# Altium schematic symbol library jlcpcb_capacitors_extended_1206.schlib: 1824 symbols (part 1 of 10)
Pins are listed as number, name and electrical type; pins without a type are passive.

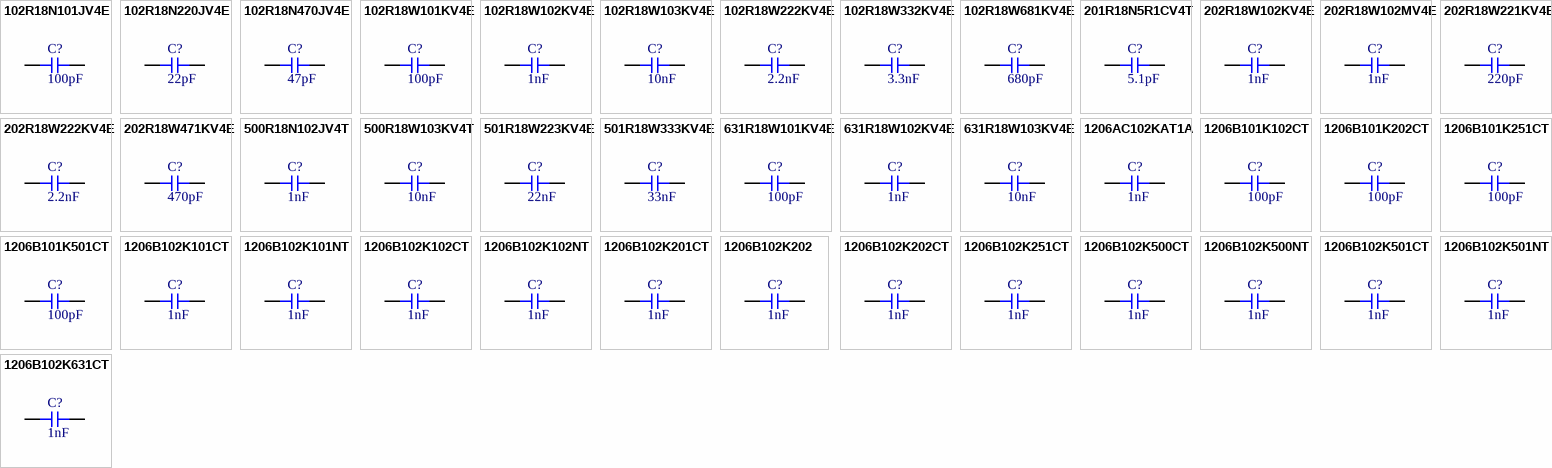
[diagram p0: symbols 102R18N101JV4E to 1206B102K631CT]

## 102R18N101JV4E
designator C?  Capacitance: 100pF  (hidden comment: *)
Capacitor, Ceramic (MLCC), 100pF, ±5%, 1kV, C0G, ±5%, SMD 1206; Manufacturer: Johanson Dielectrics; Manufacturer Part Number: 102R18N101JV4E
footprint CAP-1206 (1206 (3216M) Capacitor)
pins: 1, 2

## 102R18N220JV4E
designator C?  Capacitance: 22pF  (hidden comment: *)
Capacitor, Ceramic (MLCC), 22pF, ±5%, 1kV, NP0, ±5%, SMD 1206; Manufacturer: Johanson Dielectrics; Manufacturer Part Number: 102R18N220JV4E
footprint CAP-1206 (1206 (3216M) Capacitor)
pins: 1, 2

## 102R18N470JV4E
designator C?  Capacitance: 47pF  (hidden comment: *)
Capacitor, Ceramic (MLCC), 47pF, ±5%, 1kV, NP0, ±5%, SMD 1206; Manufacturer: Johanson Dielectrics; Manufacturer Part Number: 102R18N470JV4E
footprint CAP-1206 (1206 (3216M) Capacitor)
pins: 1, 2

## 102R18W101KV4E
designator C?  Capacitance: 100pF  (hidden comment: *)
Capacitor, Ceramic (MLCC), 100pF, ±10%, 1kV, X7R, ±10%, SMD 1206; Manufacturer: Johanson Dielectrics; Manufacturer Part Number: 102R18W101KV4E
footprint CAP-1206 (1206 (3216M) Capacitor)
pins: 1, 2

## 102R18W102KV4E
designator C?  Capacitance: 1nF  (hidden comment: *)
Capacitor, Ceramic (MLCC), 1nF, ±10%, 1kV, X7R, ±10%, SMD 1206; Manufacturer: Johanson Dielectrics; Manufacturer Part Number: 102R18W102KV4E
footprint CAP-1206 (1206 (3216M) Capacitor)
pins: 1, 2

## 102R18W103KV4E
designator C?  Capacitance: 10nF  (hidden comment: *)
Capacitor, Ceramic (MLCC), 10nF, ±10%, 1kV, X7R, ±10%, SMD 1206; Manufacturer: Johanson Dielectrics; Manufacturer Part Number: 102R18W103KV4E
footprint CAP-1206 (1206 (3216M) Capacitor)
pins: 1, 2

## 102R18W222KV4E
designator C?  Capacitance: 2.2nF  (hidden comment: *)
Capacitor, Ceramic (MLCC), 2.2nF, ±10%, 1kV, X7R, ±10%, SMD 1206; Manufacturer: Johanson Dielectrics; Manufacturer Part Number: 102R18W222KV4E
footprint CAP-1206 (1206 (3216M) Capacitor)
pins: 1, 2

## 102R18W332KV4E
designator C?  Capacitance: 3.3nF  (hidden comment: *)
Capacitor, Ceramic (MLCC), 3.3nF, ±10%, 1kV, X7R, ±10%, SMD 1206; Manufacturer: Johanson Dielectrics; Manufacturer Part Number: 102R18W332KV4E
footprint CAP-1206 (1206 (3216M) Capacitor)
pins: 1, 2

## 102R18W681KV4E
designator C?  Capacitance: 680pF  (hidden comment: *)
Capacitor, Ceramic (MLCC), 680pF, ±10%, 1kV, X7R, ±10%, SMD 1206; Manufacturer: Johanson Dielectrics; Manufacturer Part Number: 102R18W681KV4E
footprint CAP-1206 (1206 (3216M) Capacitor)
pins: 1, 2

## 201R18N5R1CV4T
designator C?  Capacitance: 5.1pF  (hidden comment: *)
Capacitor, Ceramic (MLCC), 5.1pF, ±0.25pF, 200V, NP0, ±0.25pF, SMD 1206; Manufacturer: Johanson Dielectrics; Manufacturer Part Number: 201R18N5R1CV4T
footprint CAP-1206 (1206 (3216M) Capacitor)
pins: 1, 2

## 202R18W102KV4E
designator C?  Capacitance: 1nF  (hidden comment: *)
Capacitor, Ceramic (MLCC), 1nF, ±10%, 2kV, X7R, ±10%, SMD 1206; Manufacturer: Johanson Dielectrics; Manufacturer Part Number: 202R18W102KV4E
footprint CAP-1206 (1206 (3216M) Capacitor)
pins: 1, 2

## 202R18W102MV4E
designator C?  Capacitance: 1nF  (hidden comment: *)
Capacitor, Ceramic (MLCC), 1nF, ±20%, 2kV, X7R, ±20%, SMD 1206; Manufacturer: Johanson Dielectrics; Manufacturer Part Number: 202R18W102MV4E
footprint CAP-1206 (1206 (3216M) Capacitor)
pins: 1, 2

## 202R18W221KV4E
designator C?  Capacitance: 220pF  (hidden comment: *)
Capacitor, Ceramic (MLCC), 220pF, ±10%, 2kV, X7R, ±10%, SMD 1206; Manufacturer: Johanson Dielectrics; Manufacturer Part Number: 202R18W221KV4E
footprint CAP-1206 (1206 (3216M) Capacitor)
pins: 1, 2

## 202R18W222KV4E
designator C?  Capacitance: 2.2nF  (hidden comment: *)
Capacitor, Ceramic (MLCC), 2.2nF, ±10%, 2kV, X7R, ±10%, SMD 1206; Manufacturer: Johanson Dielectrics; Manufacturer Part Number: 202R18W222KV4E
footprint CAP-1206 (1206 (3216M) Capacitor)
pins: 1, 2

## 202R18W471KV4E
designator C?  Capacitance: 470pF  (hidden comment: *)
Capacitor, Ceramic (MLCC), 470pF, ±10%, 2kV, X7R, ±10%, SMD 1206; Manufacturer: Johanson Dielectrics; Manufacturer Part Number: 202R18W471KV4E
footprint CAP-1206 (1206 (3216M) Capacitor)
pins: 1, 2

## 500R18N102JV4T
designator C?  Capacitance: 1nF  (hidden comment: *)
Capacitor, Ceramic (MLCC), 1nF, ±5%, 50V, NP0, ±5%, SMD 1206; Manufacturer: Johanson Dielectrics; Manufacturer Part Number: 500R18N102JV4T
footprint CAP-1206 (1206 (3216M) Capacitor)
pins: 1, 2

## 500R18W103KV4T
designator C?  Capacitance: 10nF  (hidden comment: *)
Capacitor, Ceramic (MLCC), 10nF, ±10%, 50V, X7R, ±10%, SMD 1206; Manufacturer: Johanson Dielectrics; Manufacturer Part Number: 500R18W103KV4T
footprint CAP-1206 (1206 (3216M) Capacitor)
pins: 1, 2

## 501R18W223KV4E
designator C?  Capacitance: 22nF  (hidden comment: *)
Capacitor, Ceramic (MLCC), 22nF, ±10%, 500V, X7R, ±10%, SMD 1206; Manufacturer: Johanson Dielectrics; Manufacturer Part Number: 501R18W223KV4E
footprint CAP-1206 (1206 (3216M) Capacitor)
pins: 1, 2

## 501R18W333KV4E
designator C?  Capacitance: 33nF  (hidden comment: *)
Capacitor, Ceramic (MLCC), 33nF, ±10%, 500V, X7R, ±10%, SMD 1206; Manufacturer: Johanson Dielectrics; Manufacturer Part Number: 501R18W333KV4E
footprint CAP-1206 (1206 (3216M) Capacitor)
pins: 1, 2

## 631R18W101KV4E
designator C?  Capacitance: 100pF  (hidden comment: *)
Capacitor, Ceramic (MLCC), 100pF, ±10%, 630V, X7R, ±10%, SMD 1206; Manufacturer: Johanson Dielectrics; Manufacturer Part Number: 631R18W101KV4E
footprint CAP-1206 (1206 (3216M) Capacitor)
pins: 1, 2

## 631R18W102KV4E
designator C?  Capacitance: 1nF  (hidden comment: *)
Capacitor, Ceramic (MLCC), 1nF, ±10%, 630V, X7R, ±10%, SMD 1206; Manufacturer: Johanson Dielectrics; Manufacturer Part Number: 631R18W102KV4E
footprint CAP-1206 (1206 (3216M) Capacitor)
pins: 1, 2

## 631R18W103KV4E
designator C?  Capacitance: 10nF  (hidden comment: *)
Capacitor, Ceramic (MLCC), 10nF, ±10%, 630V, X7R, ±10%, SMD 1206; Manufacturer: Johanson Dielectrics; Manufacturer Part Number: 631R18W103KV4E
footprint CAP-1206 (1206 (3216M) Capacitor)
pins: 1, 2

## 1206AC102KAT1A
designator C?  Capacitance: 1nF  (hidden comment: *)
Capacitor, Ceramic (MLCC), 1nF, ±10%, 1kV, X7R, ±10%, SMD 1206; Manufacturer: AVX; Manufacturer Part Number: 1206AC102KAT1A
footprint CAP-1206 (1206 (3216M) Capacitor)
pins: 1, 2

## 1206B101K102CT
designator C?  Capacitance: 100pF  (hidden comment: *)
Capacitor, Ceramic (MLCC), 100pF, ±10%, 1kV, X7R, ±10%, SMD 1206; Manufacturer: Walsin Tech Corp; Manufacturer Part Number: 1206B101K102CT
footprint CAP-1206 (1206 (3216M) Capacitor)
pins: 1, 2

## 1206B101K202CT
designator C?  Capacitance: 100pF  (hidden comment: *)
Capacitor, Ceramic (MLCC), 100pF, ±10%, 2kV, X7R, ±10%, SMD 1206; Manufacturer: Walsin Tech Corp; Manufacturer Part Number: 1206B101K202CT
footprint CAP-1206 (1206 (3216M) Capacitor)
pins: 1, 2

## 1206B101K251CT
designator C?  Capacitance: 100pF  (hidden comment: *)
Capacitor, Ceramic (MLCC), 100pF, ±10%, 250V, X7R, ±10%, SMD 1206; Manufacturer: Walsin Tech Corp; Manufacturer Part Number: 1206B101K251CT
footprint CAP-1206 (1206 (3216M) Capacitor)
pins: 1, 2

## 1206B101K501CT
designator C?  Capacitance: 100pF  (hidden comment: *)
Capacitor, Ceramic (MLCC), 100pF, ±10%, 500V, X7R, ±10%, SMD 1206; Manufacturer: Walsin Tech Corp; Manufacturer Part Number: 1206B101K501CT
footprint CAP-1206 (1206 (3216M) Capacitor)
pins: 1, 2

## 1206B102K101CT
designator C?  Capacitance: 1nF  (hidden comment: *)
Capacitor, Ceramic (MLCC), 1nF, ±10%, 100V, X7R, ±10%, SMD 1206; Manufacturer: Walsin Tech Corp; Manufacturer Part Number: 1206B102K101CT
footprint CAP-1206 (1206 (3216M) Capacitor)
pins: 1, 2

## 1206B102K101NT
designator C?  Capacitance: 1nF  (hidden comment: *)
Capacitor, Ceramic (MLCC), 1nF, ±10%, 100V, X7R, ±10%, SMD 1206; Manufacturer: FH(Guangdong Fenghua Advanced Tech); Manufacturer Part Number: 1206B102K101NT
footprint CAP-1206 (1206 (3216M) Capacitor)
pins: 1, 2

## 1206B102K102CT
designator C?  Capacitance: 1nF  (hidden comment: *)
Capacitor, Ceramic (MLCC), 1nF, ±10%, 1kV, X7R, ±10%, SMD 1206; Manufacturer: Walsin Tech Corp; Manufacturer Part Number: 1206B102K102CT
footprint CAP-1206 (1206 (3216M) Capacitor)
pins: 1, 2

## 1206B102K102NT
designator C?  Capacitance: 1nF  (hidden comment: *)
Capacitor, Ceramic (MLCC), 1nF, ±10%, 1kV, X7R, ±10%, SMD 1206; Manufacturer: FH(Guangdong Fenghua Advanced Tech); Manufacturer Part Number: 1206B102K102NT
footprint CAP-1206 (1206 (3216M) Capacitor)
pins: 1, 2

## 1206B102K201CT
designator C?  Capacitance: 1nF  (hidden comment: *)
Capacitor, Ceramic (MLCC), 1nF, ±10%, 200V, X7R, ±10%, SMD 1206; Manufacturer: Walsin Tech Corp; Manufacturer Part Number: 1206B102K201CT
footprint CAP-1206 (1206 (3216M) Capacitor)
pins: 1, 2

## 1206B102K202
designator C?  Capacitance: 1nF  (hidden comment: *)
Capacitor, Ceramic (MLCC), 1nF, ±10%, 2kV, X7R, ±10%, SMD 1206; Manufacturer: Walsin Tech Corp; Manufacturer Part Number: 1206B102K202
footprint CAP-1206 (1206 (3216M) Capacitor)
pins: 1, 2

## 1206B102K202CT
designator C?  Capacitance: 1nF  (hidden comment: *)
Capacitor, Ceramic (MLCC), 1nF, ±10%, 2kV, X7R, ±10%, SMD 1206; Manufacturer: Walsin Tech Corp; Manufacturer Part Number: 1206B102K202CT
footprint CAP-1206 (1206 (3216M) Capacitor)
pins: 1, 2

## 1206B102K251CT
designator C?  Capacitance: 1nF  (hidden comment: *)
Capacitor, Ceramic (MLCC), 1nF, ±10%, 250V, X7R, ±10%, SMD 1206; Manufacturer: Walsin Tech Corp; Manufacturer Part Number: 1206B102K251CT
footprint CAP-1206 (1206 (3216M) Capacitor)
pins: 1, 2

## 1206B102K500CT
designator C?  Capacitance: 1nF  (hidden comment: *)
Capacitor, Ceramic (MLCC), 1nF, ±10%, 50V, X7R, ±10%, SMD 1206; Manufacturer: Walsin Tech Corp; Manufacturer Part Number: 1206B102K500CT
footprint CAP-1206 (1206 (3216M) Capacitor)
pins: 1, 2

## 1206B102K500NT
designator C?  Capacitance: 1nF  (hidden comment: *)
Capacitor, Ceramic (MLCC), 1nF, ±10%, 50V, X7R, ±10%, SMD 1206; Manufacturer: FH(Guangdong Fenghua Advanced Tech); Manufacturer Part Number: 1206B102K500NT
footprint CAP-1206 (1206 (3216M) Capacitor)
pins: 1, 2

## 1206B102K501CT
designator C?  Capacitance: 1nF  (hidden comment: *)
Capacitor, Ceramic (MLCC), 1nF, ±10%, 500V, X7R, ±10%, SMD 1206; Manufacturer: Walsin Tech Corp; Manufacturer Part Number: 1206B102K501CT
footprint CAP-1206 (1206 (3216M) Capacitor)
pins: 1, 2

## 1206B102K501NT
designator C?  Capacitance: 1nF  (hidden comment: *)
Capacitor, Ceramic (MLCC), 1nF, ±10%, 500V, X7R, ±10%, SMD 1206; Manufacturer: FH(Guangdong Fenghua Advanced Tech); Manufacturer Part Number: 1206B102K501NT
footprint CAP-1206 (1206 (3216M) Capacitor)
pins: 1, 2

## 1206B102K631CT
designator C?  Capacitance: 1nF  (hidden comment: *)
Capacitor, Ceramic (MLCC), 1nF, ±10%, 630V, X7R, ±10%, SMD 1206; Manufacturer: Walsin Tech Corp; Manufacturer Part Number: 1206B102K631CT
footprint CAP-1206 (1206 (3216M) Capacitor)
pins: 1, 2

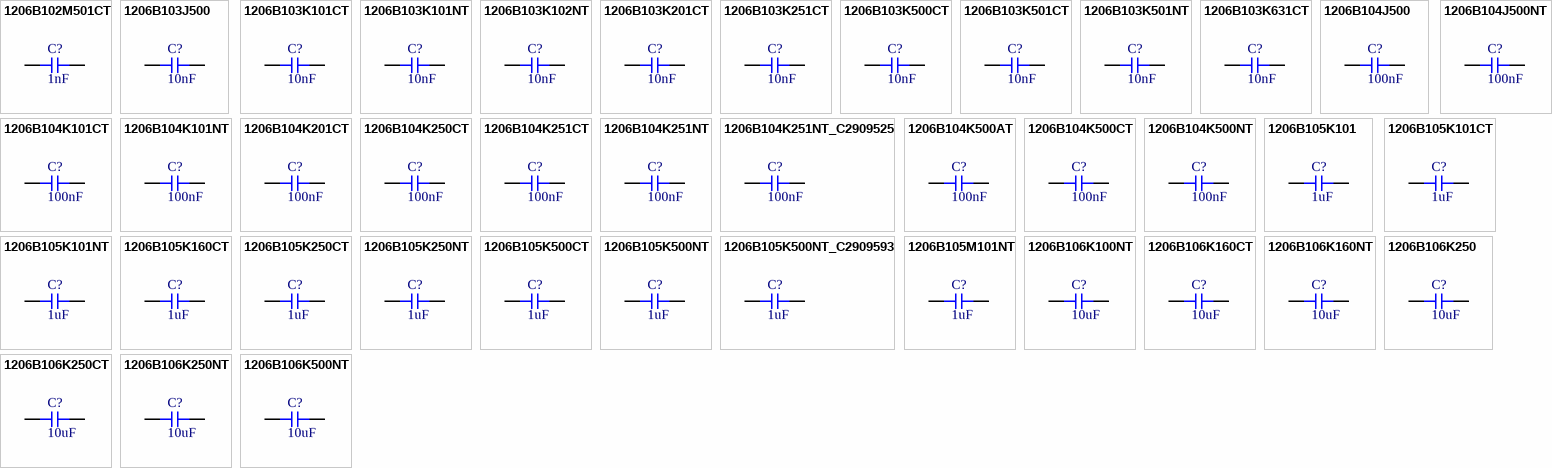
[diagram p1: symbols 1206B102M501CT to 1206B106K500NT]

## 1206B102M501CT
designator C?  Capacitance: 1nF  (hidden comment: *)
Capacitor, Ceramic (MLCC), 1nF, ±20%, 500V, X7R, ±20%, SMD 1206; Manufacturer: Walsin Tech Corp; Manufacturer Part Number: 1206B102M501CT
footprint CAP-1206 (1206 (3216M) Capacitor)
pins: 1, 2

## 1206B103J500
designator C?  Capacitance: 10nF  (hidden comment: *)
Capacitor, Ceramic (MLCC), 10nF, ±5%, 50V, X7R, ±5%, SMD 1206; Manufacturer: Walsin Tech Corp; Manufacturer Part Number: 1206B103J500
footprint CAP-1206 (1206 (3216M) Capacitor)
pins: 1, 2

## 1206B103K101CT
designator C?  Capacitance: 10nF  (hidden comment: *)
Capacitor, Ceramic (MLCC), 10nF, ±10%, 100V, X7R, ±10%, SMD 1206; Manufacturer: Walsin Tech Corp; Manufacturer Part Number: 1206B103K101CT
footprint CAP-1206 (1206 (3216M) Capacitor)
pins: 1, 2

## 1206B103K101NT
designator C?  Capacitance: 10nF  (hidden comment: *)
Capacitor, Ceramic (MLCC), 10nF, ±10%, 100V, X7R, ±10%, SMD 1206; Manufacturer: FH(Guangdong Fenghua Advanced Tech); Manufacturer Part Number: 1206B103K101NT
footprint CAP-1206 (1206 (3216M) Capacitor)
pins: 1, 2

## 1206B103K102NT
designator C?  Capacitance: 10nF  (hidden comment: *)
Capacitor, Ceramic (MLCC), 10nF, ±10%, 1kV, X7R, ±10%, SMD 1206; Manufacturer: FH(Guangdong Fenghua Advanced Tech); Manufacturer Part Number: 1206B103K102NT
footprint CAP-1206 (1206 (3216M) Capacitor)
pins: 1, 2

## 1206B103K201CT
designator C?  Capacitance: 10nF  (hidden comment: *)
Capacitor, Ceramic (MLCC), 10nF, ±10%, 200V, X7R, ±10%, SMD 1206; Manufacturer: Walsin Tech Corp; Manufacturer Part Number: 1206B103K201CT
footprint CAP-1206 (1206 (3216M) Capacitor)
pins: 1, 2

## 1206B103K251CT
designator C?  Capacitance: 10nF  (hidden comment: *)
Capacitor, Ceramic (MLCC), 10nF, ±10%, 250V, X7R, ±10%, SMD 1206; Manufacturer: Walsin Tech Corp; Manufacturer Part Number: 1206B103K251CT
footprint CAP-1206 (1206 (3216M) Capacitor)
pins: 1, 2

## 1206B103K500CT
designator C?  Capacitance: 10nF  (hidden comment: *)
Capacitor, Ceramic (MLCC), 10nF, ±10%, 50V, X7R, ±10%, SMD 1206; Manufacturer: Walsin Tech Corp; Manufacturer Part Number: 1206B103K500CT
footprint CAP-1206 (1206 (3216M) Capacitor)
pins: 1, 2

## 1206B103K501CT
designator C?  Capacitance: 10nF  (hidden comment: *)
Capacitor, Ceramic (MLCC), 10nF, ±10%, 500V, X7R, ±10%, SMD 1206; Manufacturer: Walsin Tech Corp; Manufacturer Part Number: 1206B103K501CT
footprint CAP-1206 (1206 (3216M) Capacitor)
pins: 1, 2

## 1206B103K501NT
designator C?  Capacitance: 10nF  (hidden comment: *)
Capacitor, Ceramic (MLCC), 10nF, ±10%, 500V, X7R, ±10%, SMD 1206; Manufacturer: FH(Guangdong Fenghua Advanced Tech); Manufacturer Part Number: 1206B103K501NT
footprint CAP-1206 (1206 (3216M) Capacitor)
pins: 1, 2

## 1206B103K631CT
designator C?  Capacitance: 10nF  (hidden comment: *)
Capacitor, Ceramic (MLCC), 10nF, ±10%, 630V, X7R, ±10%, SMD 1206; Manufacturer: Walsin Tech Corp; Manufacturer Part Number: 1206B103K631CT
footprint CAP-1206 (1206 (3216M) Capacitor)
pins: 1, 2

## 1206B104J500
designator C?  Capacitance: 100nF  (hidden comment: *)
Capacitor, Ceramic (MLCC), 100nF, ±5%, 50V, X7R, ±5%, SMD 1206; Manufacturer: Walsin Tech Corp; Manufacturer Part Number: 1206B104J500
footprint CAP-1206 (1206 (3216M) Capacitor)
pins: 1, 2

## 1206B104J500NT
designator C?  Capacitance: 100nF  (hidden comment: *)
Capacitor, Ceramic (MLCC), 100nF, ±5%, 50V, ±5%, SMD 1206; Manufacturer: FH(Guangdong Fenghua Advanced Tech); Manufacturer Part Number: 1206B104J500NT
footprint CAP-1206 (1206 (3216M) Capacitor)
pins: 1, 2

## 1206B104K101CT
designator C?  Capacitance: 100nF  (hidden comment: *)
Capacitor, Ceramic (MLCC), 100nF, ±10%, 100V, X7R, ±10%, SMD 1206; Manufacturer: Walsin Tech Corp; Manufacturer Part Number: 1206B104K101CT
footprint CAP-1206 (1206 (3216M) Capacitor)
pins: 1, 2

## 1206B104K101NT
designator C?  Capacitance: 100nF  (hidden comment: *)
Capacitor, Ceramic (MLCC), 100nF, ±10%, 100V, X7R, ±10%, SMD 1206; Manufacturer: FH(Guangdong Fenghua Advanced Tech); Manufacturer Part Number: 1206B104K101NT
footprint CAP-1206 (1206 (3216M) Capacitor)
pins: 1, 2

## 1206B104K201CT
designator C?  Capacitance: 100nF  (hidden comment: *)
Capacitor, Ceramic (MLCC), 100nF, ±10%, 200V, X7R, ±10%, SMD 1206; Manufacturer: Walsin Tech Corp; Manufacturer Part Number: 1206B104K201CT
footprint CAP-1206 (1206 (3216M) Capacitor)
pins: 1, 2

## 1206B104K250CT
designator C?  Capacitance: 100nF  (hidden comment: *)
Capacitor, Ceramic (MLCC), 100nF, ±10%, 25V, X7R, ±10%, SMD 1206; Manufacturer: Walsin Tech Corp; Manufacturer Part Number: 1206B104K250CT
footprint CAP-1206 (1206 (3216M) Capacitor)
pins: 1, 2

## 1206B104K251CT
designator C?  Capacitance: 100nF  (hidden comment: *)
Capacitor, Ceramic (MLCC), 100nF, ±10%, 250V, X7R, ±10%, SMD 1206; Manufacturer: Walsin Tech Corp; Manufacturer Part Number: 1206B104K251CT
footprint CAP-1206 (1206 (3216M) Capacitor)
pins: 1, 2

## 1206B104K251NT
designator C?  Capacitance: 100nF  (hidden comment: *)
Capacitor, Ceramic (MLCC), 100nF, ±10%, 250V, X7R, ±10%, SMD 1206; Manufacturer: FH(Guangdong Fenghua Advanced Tech); Manufacturer Part Number: 1206B104K251NT
footprint CAP-1206 (1206 (3216M) Capacitor)
pins: 1, 2

## 1206B104K251NT_C2909525
designator C?  Capacitance: 100nF  (hidden comment: *)
Capacitor, Ceramic (MLCC), 100nF, ±10%, 250V, X7R, ±10%, SMD 1206; Manufacturer: FH(Guangdong Fenghua Advanced Tech); Manufacturer Part Number: 1206B104K251NT
footprint CAP-1206 (1206 (3216M) Capacitor)
pins: 1, 2

## 1206B104K500AT
designator C?  Capacitance: 100nF  (hidden comment: *)
Capacitor, Ceramic (MLCC), 100nF, ±10%, 50V, X7R, ±10%, SMD 1206; Manufacturer: FH(Guangdong Fenghua Advanced Tech); Manufacturer Part Number: 1206B104K500AT
footprint CAP-1206 (1206 (3216M) Capacitor)
pins: 1, 2

## 1206B104K500CT
designator C?  Capacitance: 100nF  (hidden comment: *)
Capacitor, Ceramic (MLCC), 100nF, ±10%, 50V, X7R, ±10%, SMD 1206; Manufacturer: Walsin Tech Corp; Manufacturer Part Number: 1206B104K500CT
footprint CAP-1206 (1206 (3216M) Capacitor)
pins: 1, 2

## 1206B104K500NT
designator C?  Capacitance: 100nF  (hidden comment: *)
Capacitor, Ceramic (MLCC), 100nF, ±10%, 50V, X7R, ±10%, SMD 1206; Manufacturer: FH(Guangdong Fenghua Advanced Tech); Manufacturer Part Number: 1206B104K500NT
footprint CAP-1206 (1206 (3216M) Capacitor)
pins: 1, 2

## 1206B105K101
designator C?  Capacitance: 1uF  (hidden comment: *)
Capacitor, Ceramic (MLCC), 1uF, ±10%, 100V, X7R, ±10%, SMD 1206; Manufacturer: Walsin Tech Corp; Manufacturer Part Number: 1206B105K101
footprint CAP-1206 (1206 (3216M) Capacitor)
pins: 1, 2

## 1206B105K101CT
designator C?  Capacitance: 1uF  (hidden comment: *)
Capacitor, Ceramic (MLCC), 1uF, ±10%, 100V, X7R, ±10%, SMD 1206; Manufacturer: Walsin Tech Corp; Manufacturer Part Number: 1206B105K101CT
footprint CAP-1206 (1206 (3216M) Capacitor)
pins: 1, 2

## 1206B105K101NT
designator C?  Capacitance: 1uF  (hidden comment: *)
Capacitor, Ceramic (MLCC), 1uF, ±10%, 100V, X7R, ±10%, SMD 1206; Manufacturer: FH(Guangdong Fenghua Advanced Tech); Manufacturer Part Number: 1206B105K101NT
footprint CAP-1206 (1206 (3216M) Capacitor)
pins: 1, 2

## 1206B105K160CT
designator C?  Capacitance: 1uF  (hidden comment: *)
Capacitor, Ceramic (MLCC), 1uF, ±10%, 16V, X7R, ±10%, SMD 1206; Manufacturer: Walsin Tech Corp; Manufacturer Part Number: 1206B105K160CT
footprint CAP-1206 (1206 (3216M) Capacitor)
pins: 1, 2

## 1206B105K250CT
designator C?  Capacitance: 1uF  (hidden comment: *)
Capacitor, Ceramic (MLCC), 1uF, ±10%, 25V, X7R, ±10%, SMD 1206; Manufacturer: Walsin Tech Corp; Manufacturer Part Number: 1206B105K250CT
footprint CAP-1206 (1206 (3216M) Capacitor)
pins: 1, 2

## 1206B105K250NT
designator C?  Capacitance: 1uF  (hidden comment: *)
Capacitor, Ceramic (MLCC), 1uF, ±10%, 25V, X7R, ±10%, SMD 1206; Manufacturer: FH(Guangdong Fenghua Advanced Tech); Manufacturer Part Number: 1206B105K250NT
footprint CAP-1206 (1206 (3216M) Capacitor)
pins: 1, 2

## 1206B105K500CT
designator C?  Capacitance: 1uF  (hidden comment: *)
Capacitor, Ceramic (MLCC), 1uF, ±10%, 50V, X7R, ±10%, SMD 1206; Manufacturer: Walsin Tech Corp; Manufacturer Part Number: 1206B105K500CT
footprint CAP-1206 (1206 (3216M) Capacitor)
pins: 1, 2

## 1206B105K500NT
designator C?  Capacitance: 1uF  (hidden comment: *)
Capacitor, Ceramic (MLCC), 1uF, ±10%, 50V, X7R, ±10%, SMD 1206; Manufacturer: FH(Guangdong Fenghua Advanced Tech); Manufacturer Part Number: 1206B105K500NT
footprint CAP-1206 (1206 (3216M) Capacitor)
pins: 1, 2

## 1206B105K500NT_C2909593
designator C?  Capacitance: 1uF  (hidden comment: *)
Capacitor, Ceramic (MLCC), 1uF, ±10%, 50V, X7R, ±10%, SMD 1206; Manufacturer: FH (Guangdong Fenghua Advanced Tech); Manufacturer Part Number: 1206B105K500NT
footprint CAP-1206 (1206 (3216M) Capacitor)
pins: 1, 2

## 1206B105M101NT
designator C?  Capacitance: 1uF  (hidden comment: *)
Capacitor, Ceramic (MLCC), 1uF, ±20%, 100V, ±20%, SMD 1206; Manufacturer: FH (Guangdong Fenghua Advanced Tech); Manufacturer Part Number: 1206B105M101NT
footprint CAP-1206 (1206 (3216M) Capacitor)
pins: 1, 2

## 1206B106K100NT
designator C?  Capacitance: 10uF  (hidden comment: *)
Capacitor, Ceramic (MLCC), 10uF, ±10%, 10V, X7R, ±10%, SMD 1206; Manufacturer: FH(Guangdong Fenghua Advanced Tech); Manufacturer Part Number: 1206B106K100NT
footprint CAP-1206 (1206 (3216M) Capacitor)
pins: 1, 2

## 1206B106K160CT
designator C?  Capacitance: 10uF  (hidden comment: *)
Capacitor, Ceramic (MLCC), 10uF, ±10%, 16V, X7R, ±10%, SMD 1206; Manufacturer: Walsin Tech Corp; Manufacturer Part Number: 1206B106K160CT
footprint CAP-1206 (1206 (3216M) Capacitor)
pins: 1, 2

## 1206B106K160NT
designator C?  Capacitance: 10uF  (hidden comment: *)
Capacitor, Ceramic (MLCC), 10uF, ±10%, 16V, X7R, ±10%, SMD 1206; Manufacturer: FH(Guangdong Fenghua Advanced Tech); Manufacturer Part Number: 1206B106K160NT
footprint CAP-1206 (1206 (3216M) Capacitor)
pins: 1, 2

## 1206B106K250
designator C?  Capacitance: 10uF  (hidden comment: *)
Capacitor, Ceramic (MLCC), 10uF, ±10%, 25V, X7R, ±10%, SMD 1206; Manufacturer: Walsin Tech Corp; Manufacturer Part Number: 1206B106K250
footprint CAP-1206 (1206 (3216M) Capacitor)
pins: 1, 2

## 1206B106K250CT
designator C?  Capacitance: 10uF  (hidden comment: *)
Capacitor, Ceramic (MLCC), 10uF, ±10%, 25V, X7R, ±10%, SMD 1206; Manufacturer: Walsin Tech Corp; Manufacturer Part Number: 1206B106K250CT
footprint CAP-1206 (1206 (3216M) Capacitor)
pins: 1, 2

## 1206B106K250NT
designator C?  Capacitance: 10uF  (hidden comment: *)
Capacitor, Ceramic (MLCC), 10uF, ±10%, 25V, X7R, ±10%, SMD 1206; Manufacturer: FH(Guangdong Fenghua Advanced Tech); Manufacturer Part Number: 1206B106K250NT
footprint CAP-1206 (1206 (3216M) Capacitor)
pins: 1, 2

## 1206B106K500NT
designator C?  Capacitance: 10uF  (hidden comment: *)
Capacitor, Ceramic (MLCC), 10uF, ±10%, 50V, X7R, ±10%, SMD 1206; Manufacturer: FH(Guangdong Fenghua Advanced Tech); Manufacturer Part Number: 1206B106K500NT
footprint CAP-1206 (1206 (3216M) Capacitor)
pins: 1, 2

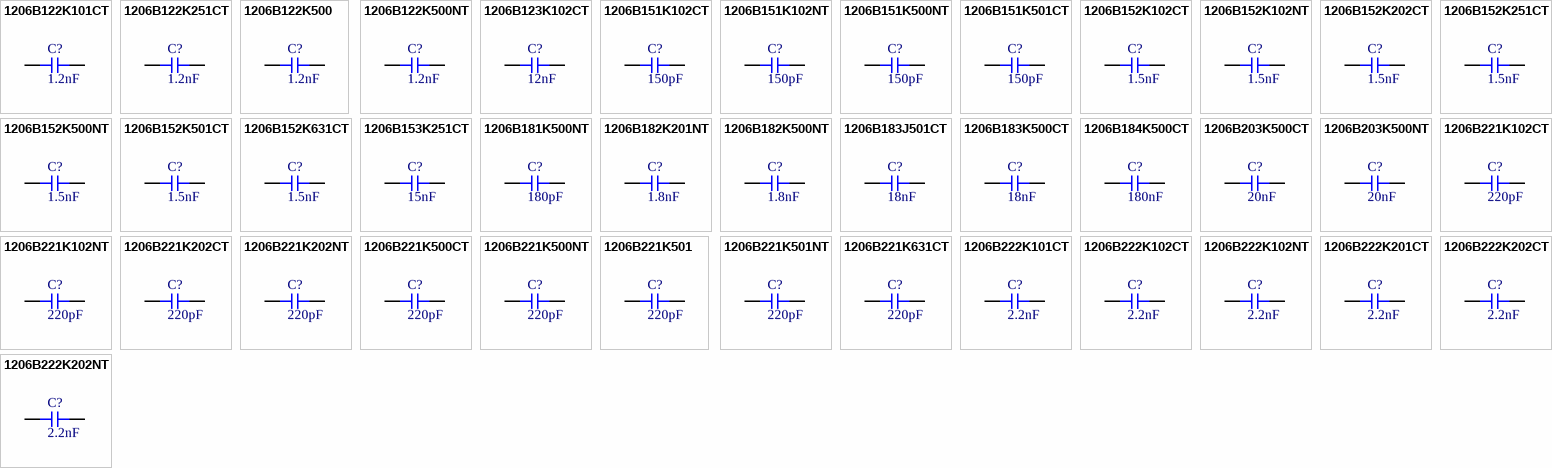
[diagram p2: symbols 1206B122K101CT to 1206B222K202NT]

## 1206B122K101CT
designator C?  Capacitance: 1.2nF  (hidden comment: *)
Capacitor, Ceramic (MLCC), 1.2nF, ±10%, 100V, X7R, ±10%, SMD 1206; Manufacturer: Walsin Tech Corp; Manufacturer Part Number: 1206B122K101CT
footprint CAP-1206 (1206 (3216M) Capacitor)
pins: 1, 2

## 1206B122K251CT
designator C?  Capacitance: 1.2nF  (hidden comment: *)
Capacitor, Ceramic (MLCC), 1.2nF, ±10%, 250V, X7R, ±10%, SMD 1206; Manufacturer: Walsin Tech Corp; Manufacturer Part Number: 1206B122K251CT
footprint CAP-1206 (1206 (3216M) Capacitor)
pins: 1, 2

## 1206B122K500
designator C?  Capacitance: 1.2nF  (hidden comment: *)
Capacitor, Ceramic (MLCC), 1.2nF, ±10%, 50V, X7R, ±10%, SMD 1206; Manufacturer: Walsin Tech Corp; Manufacturer Part Number: 1206B122K500
footprint CAP-1206 (1206 (3216M) Capacitor)
pins: 1, 2

## 1206B122K500NT
designator C?  Capacitance: 1.2nF  (hidden comment: *)
Capacitor, Ceramic (MLCC), 1.2nF, ±10%, 50V, X7R, ±10%, SMD 1206; Manufacturer: FH(Guangdong Fenghua Advanced Tech); Manufacturer Part Number: 1206B122K500NT
footprint CAP-1206 (1206 (3216M) Capacitor)
pins: 1, 2

## 1206B123K102CT
designator C?  Capacitance: 12nF  (hidden comment: *)
Capacitor, Ceramic (MLCC), 12nF, ±10%, 1kV, X7R, ±10%, SMD 1206; Manufacturer: Walsin Tech Corp; Manufacturer Part Number: 1206B123K102CT
footprint CAP-1206 (1206 (3216M) Capacitor)
pins: 1, 2

## 1206B151K102CT
designator C?  Capacitance: 150pF  (hidden comment: *)
Capacitor, Ceramic (MLCC), 150pF, ±10%, 1kV, X7R, ±10%, SMD 1206; Manufacturer: Walsin Tech Corp; Manufacturer Part Number: 1206B151K102CT
footprint CAP-1206 (1206 (3216M) Capacitor)
pins: 1, 2

## 1206B151K102NT
designator C?  Capacitance: 150pF  (hidden comment: *)
Capacitor, Ceramic (MLCC), 150pF, ±10%, 1kV, X7R, ±10%, SMD 1206; Manufacturer: FH(Guangdong Fenghua Advanced Tech); Manufacturer Part Number: 1206B151K102NT
footprint CAP-1206 (1206 (3216M) Capacitor)
pins: 1, 2

## 1206B151K500NT
designator C?  Capacitance: 150pF  (hidden comment: *)
Capacitor, Ceramic (MLCC), 150pF, ±10%, 50V, X7R, ±10%, SMD 1206; Manufacturer: FH(Guangdong Fenghua Advanced Tech); Manufacturer Part Number: 1206B151K500NT
footprint CAP-1206 (1206 (3216M) Capacitor)
pins: 1, 2

## 1206B151K501CT
designator C?  Capacitance: 150pF  (hidden comment: *)
Capacitor, Ceramic (MLCC), 150pF, ±10%, 500V, X7R, ±10%, SMD 1206; Manufacturer: Walsin Tech Corp; Manufacturer Part Number: 1206B151K501CT
footprint CAP-1206 (1206 (3216M) Capacitor)
pins: 1, 2

## 1206B152K102CT
designator C?  Capacitance: 1.5nF  (hidden comment: *)
Capacitor, Ceramic (MLCC), 1.5nF, ±10%, 1kV, X7R, ±10%, SMD 1206; Manufacturer: Walsin Tech Corp; Manufacturer Part Number: 1206B152K102CT
footprint CAP-1206 (1206 (3216M) Capacitor)
pins: 1, 2

## 1206B152K102NT
designator C?  Capacitance: 1.5nF  (hidden comment: *)
Capacitor, Ceramic (MLCC), 1.5nF, ±10%, 1kV, X7R, ±10%, SMD 1206; Manufacturer: FH(Guangdong Fenghua Advanced Tech); Manufacturer Part Number: 1206B152K102NT
footprint CAP-1206 (1206 (3216M) Capacitor)
pins: 1, 2

## 1206B152K202CT
designator C?  Capacitance: 1.5nF  (hidden comment: *)
Capacitor, Ceramic (MLCC), 1.5nF, ±10%, 2kV, X7R, ±10%, SMD 1206; Manufacturer: Walsin Tech Corp; Manufacturer Part Number: 1206B152K202CT
footprint CAP-1206 (1206 (3216M) Capacitor)
pins: 1, 2

## 1206B152K251CT
designator C?  Capacitance: 1.5nF  (hidden comment: *)
Capacitor, Ceramic (MLCC), 1.5nF, ±10%, 250V, X7R, ±10%, SMD 1206; Manufacturer: Walsin Tech Corp; Manufacturer Part Number: 1206B152K251CT
footprint CAP-1206 (1206 (3216M) Capacitor)
pins: 1, 2

## 1206B152K500NT
designator C?  Capacitance: 1.5nF  (hidden comment: *)
Capacitor, Ceramic (MLCC), 1.5nF, ±10%, 50V, X7R, ±10%, SMD 1206; Manufacturer: FH(Guangdong Fenghua Advanced Tech); Manufacturer Part Number: 1206B152K500NT
footprint CAP-1206 (1206 (3216M) Capacitor)
pins: 1, 2

## 1206B152K501CT
designator C?  Capacitance: 1.5nF  (hidden comment: *)
Capacitor, Ceramic (MLCC), 1.5nF, ±10%, 500V, X7R, ±10%, SMD 1206; Manufacturer: Walsin Tech Corp; Manufacturer Part Number: 1206B152K501CT
footprint CAP-1206 (1206 (3216M) Capacitor)
pins: 1, 2

## 1206B152K631CT
designator C?  Capacitance: 1.5nF  (hidden comment: *)
Capacitor, Ceramic (MLCC), 1.5nF, ±10%, 630V, X7R, ±10%, SMD 1206; Manufacturer: Walsin Tech Corp; Manufacturer Part Number: 1206B152K631CT
footprint CAP-1206 (1206 (3216M) Capacitor)
pins: 1, 2

## 1206B153K251CT
designator C?  Capacitance: 15nF  (hidden comment: *)
Capacitor, Ceramic (MLCC), 15nF, ±10%, 250V, X7R, ±10%, SMD 1206; Manufacturer: Walsin Tech Corp; Manufacturer Part Number: 1206B153K251CT
footprint CAP-1206 (1206 (3216M) Capacitor)
pins: 1, 2

## 1206B181K500NT
designator C?  Capacitance: 180pF  (hidden comment: *)
Capacitor, Ceramic (MLCC), 180pF, ±10%, 50V, X7R, ±10%, SMD 1206; Manufacturer: FH(Guangdong Fenghua Advanced Tech); Manufacturer Part Number: 1206B181K500NT
footprint CAP-1206 (1206 (3216M) Capacitor)
pins: 1, 2

## 1206B182K201NT
designator C?  Capacitance: 1.8nF  (hidden comment: *)
Capacitor, Ceramic (MLCC), 1.8nF, ±10%, 200V, X7R, ±10%, SMD 1206; Manufacturer: FH(Guangdong Fenghua Advanced Tech); Manufacturer Part Number: 1206B182K201NT
footprint CAP-1206 (1206 (3216M) Capacitor)
pins: 1, 2

## 1206B182K500NT
designator C?  Capacitance: 1.8nF  (hidden comment: *)
Capacitor, Ceramic (MLCC), 1.8nF, ±10%, 50V, X7R, ±10%, SMD 1206; Manufacturer: FH(Guangdong Fenghua Advanced Tech); Manufacturer Part Number: 1206B182K500NT
footprint CAP-1206 (1206 (3216M) Capacitor)
pins: 1, 2

## 1206B183J501CT
designator C?  Capacitance: 18nF  (hidden comment: *)
Capacitor, Ceramic (MLCC), 18nF, ±5%, 500V, X7R, ±5%, SMD 1206; Manufacturer: Walsin Tech Corp; Manufacturer Part Number: 1206B183J501CT
footprint CAP-1206 (1206 (3216M) Capacitor)
pins: 1, 2

## 1206B183K500CT
designator C?  Capacitance: 18nF  (hidden comment: *)
Capacitor, Ceramic (MLCC), 18nF, ±10%, 50V, X7R, ±10%, SMD 1206; Manufacturer: Walsin Tech Corp; Manufacturer Part Number: 1206B183K500CT
footprint CAP-1206 (1206 (3216M) Capacitor)
pins: 1, 2

## 1206B184K500CT
designator C?  Capacitance: 180nF  (hidden comment: *)
Capacitor, Ceramic (MLCC), 180nF, ±10%, 50V, X7R, ±10%, SMD 1206; Manufacturer: Walsin Tech Corp; Manufacturer Part Number: 1206B184K500CT
footprint CAP-1206 (1206 (3216M) Capacitor)
pins: 1, 2

## 1206B203K500CT
designator C?  Capacitance: 20nF  (hidden comment: *)
Capacitor, Ceramic (MLCC), 20nF, ±10%, 50V, X7R, ±10%, SMD 1206; Manufacturer: Walsin Tech Corp; Manufacturer Part Number: 1206B203K500CT
footprint CAP-1206 (1206 (3216M) Capacitor)
pins: 1, 2

## 1206B203K500NT
designator C?  Capacitance: 20nF  (hidden comment: *)
Capacitor, Ceramic (MLCC), 20nF, ±10%, 50V, X7R, ±10%, SMD 1206; Manufacturer: FH(Guangdong Fenghua Advanced Tech); Manufacturer Part Number: 1206B203K500NT
footprint CAP-1206 (1206 (3216M) Capacitor)
pins: 1, 2

## 1206B221K102CT
designator C?  Capacitance: 220pF  (hidden comment: *)
Capacitor, Ceramic (MLCC), 220pF, ±10%, 1kV, X7R, ±10%, SMD 1206; Manufacturer: Walsin Tech Corp; Manufacturer Part Number: 1206B221K102CT
footprint CAP-1206 (1206 (3216M) Capacitor)
pins: 1, 2

## 1206B221K102NT
designator C?  Capacitance: 220pF  (hidden comment: *)
Capacitor, Ceramic (MLCC), 220pF, ±10%, 1kV, X7R, ±10%, SMD 1206; Manufacturer: FH(Guangdong Fenghua Advanced Tech); Manufacturer Part Number: 1206B221K102NT
footprint CAP-1206 (1206 (3216M) Capacitor)
pins: 1, 2

## 1206B221K202CT
designator C?  Capacitance: 220pF  (hidden comment: *)
Capacitor, Ceramic (MLCC), 220pF, ±10%, 2kV, X7R, ±10%, SMD 1206; Manufacturer: Walsin Tech Corp; Manufacturer Part Number: 1206B221K202CT
footprint CAP-1206 (1206 (3216M) Capacitor)
pins: 1, 2

## 1206B221K202NT
designator C?  Capacitance: 220pF  (hidden comment: *)
Capacitor, Ceramic (MLCC), 220pF, ±10%, 2kV, X7R, ±10%, SMD 1206; Manufacturer: FH(Guangdong Fenghua Advanced Tech); Manufacturer Part Number: 1206B221K202NT
footprint CAP-1206 (1206 (3216M) Capacitor)
pins: 1, 2

## 1206B221K500CT
designator C?  Capacitance: 220pF  (hidden comment: *)
Capacitor, Ceramic (MLCC), 220pF, ±10%, 50V, X7R, ±10%, SMD 1206; Manufacturer: Walsin Tech Corp; Manufacturer Part Number: 1206B221K500CT
footprint CAP-1206 (1206 (3216M) Capacitor)
pins: 1, 2

## 1206B221K500NT
designator C?  Capacitance: 220pF  (hidden comment: *)
Capacitor, Ceramic (MLCC), 220pF, ±10%, 50V, X7R, ±10%, SMD 1206; Manufacturer: FH(Guangdong Fenghua Advanced Tech); Manufacturer Part Number: 1206B221K500NT
footprint CAP-1206 (1206 (3216M) Capacitor)
pins: 1, 2

## 1206B221K501
designator C?  Capacitance: 220pF  (hidden comment: *)
Capacitor, Ceramic (MLCC), 220pF, ±10%, 500V, X7R, ±10%, SMD 1206; Manufacturer: Walsin Tech Corp; Manufacturer Part Number: 1206B221K501
footprint CAP-1206 (1206 (3216M) Capacitor)
pins: 1, 2

## 1206B221K501NT
designator C?  Capacitance: 220pF  (hidden comment: *)
Capacitor, Ceramic (MLCC), 220pF, ±10%, 500V, X7R, ±10%, SMD 1206; Manufacturer: FH(Guangdong Fenghua Advanced Tech); Manufacturer Part Number: 1206B221K501NT
footprint CAP-1206 (1206 (3216M) Capacitor)
pins: 1, 2

## 1206B221K631CT
designator C?  Capacitance: 220pF  (hidden comment: *)
Capacitor, Ceramic (MLCC), 220pF, ±10%, 630V, X7R, ±10%, SMD 1206; Manufacturer: Walsin Tech Corp; Manufacturer Part Number: 1206B221K631CT
footprint CAP-1206 (1206 (3216M) Capacitor)
pins: 1, 2

## 1206B222K101CT
designator C?  Capacitance: 2.2nF  (hidden comment: *)
Capacitor, Ceramic (MLCC), 2.2nF, ±10%, 100V, X7R, ±10%, SMD 1206; Manufacturer: Walsin Tech Corp; Manufacturer Part Number: 1206B222K101CT
footprint CAP-1206 (1206 (3216M) Capacitor)
pins: 1, 2

## 1206B222K102CT
designator C?  Capacitance: 2.2nF  (hidden comment: *)
Capacitor, Ceramic (MLCC), 2.2nF, ±10%, 1kV, X7R, ±10%, SMD 1206; Manufacturer: Walsin Tech Corp; Manufacturer Part Number: 1206B222K102CT
footprint CAP-1206 (1206 (3216M) Capacitor)
pins: 1, 2

## 1206B222K102NT
designator C?  Capacitance: 2.2nF  (hidden comment: *)
Capacitor, Ceramic (MLCC), 2.2nF, ±10%, 1kV, X7R, ±10%, SMD 1206; Manufacturer: FH (Guangdong Fenghua Advanced Tech); Manufacturer Part Number: 1206B222K102NT
footprint CAP-1206 (1206 (3216M) Capacitor)
pins: 1, 2

## 1206B222K201CT
designator C?  Capacitance: 2.2nF  (hidden comment: *)
Capacitor, Ceramic (MLCC), 2.2nF, ±10%, 200V, X7R, ±10%, SMD 1206; Manufacturer: Walsin Tech Corp; Manufacturer Part Number: 1206B222K201CT
footprint CAP-1206 (1206 (3216M) Capacitor)
pins: 1, 2

## 1206B222K202CT
designator C?  Capacitance: 2.2nF  (hidden comment: *)
Capacitor, Ceramic (MLCC), 2.2nF, ±10%, 2kV, X7R, ±10%, SMD 1206; Manufacturer: Walsin Tech Corp; Manufacturer Part Number: 1206B222K202CT
footprint CAP-1206 (1206 (3216M) Capacitor)
pins: 1, 2

## 1206B222K202NT
designator C?  Capacitance: 2.2nF  (hidden comment: *)
Capacitor, Ceramic (MLCC), 2.2nF, ±10%, 2kV, X7R, ±10%, SMD 1206; Manufacturer: FH(Guangdong Fenghua Advanced Tech); Manufacturer Part Number: 1206B222K202NT
footprint CAP-1206 (1206 (3216M) Capacitor)
pins: 1, 2

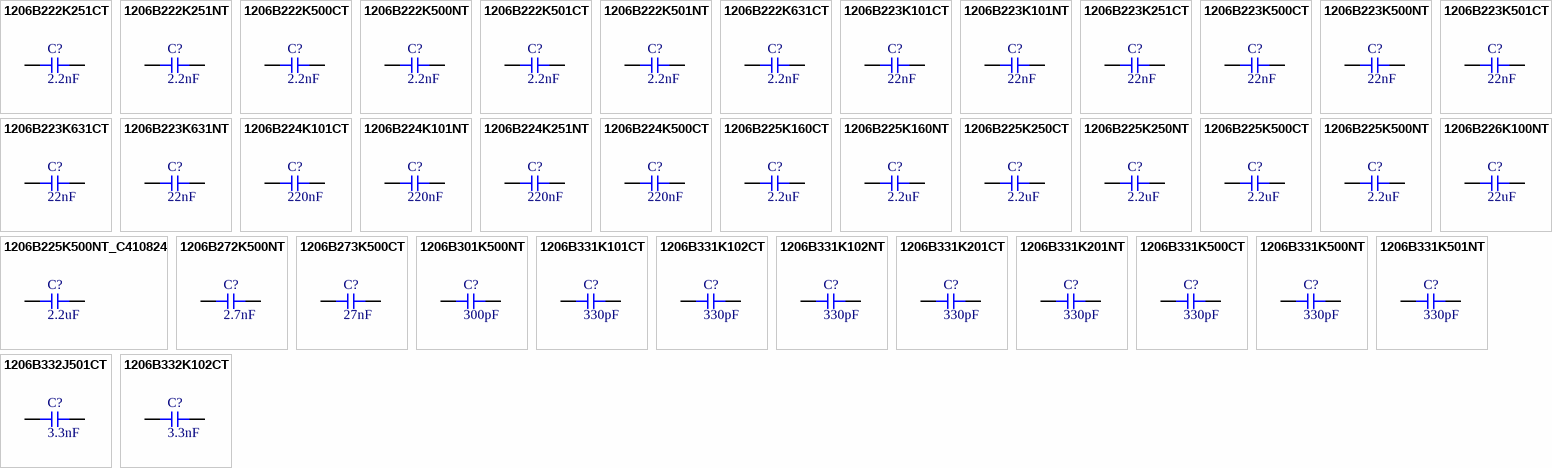
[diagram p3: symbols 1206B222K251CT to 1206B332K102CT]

## 1206B222K251CT
designator C?  Capacitance: 2.2nF  (hidden comment: *)
Capacitor, Ceramic (MLCC), 2.2nF, ±10%, 250V, X7R, ±10%, SMD 1206; Manufacturer: Walsin Tech Corp; Manufacturer Part Number: 1206B222K251CT
footprint CAP-1206 (1206 (3216M) Capacitor)
pins: 1, 2

## 1206B222K251NT
designator C?  Capacitance: 2.2nF  (hidden comment: *)
Capacitor, Ceramic (MLCC), 2.2nF, ±10%, 250V, X7R, ±10%, SMD 1206; Manufacturer: FH(Guangdong Fenghua Advanced Tech); Manufacturer Part Number: 1206B222K251NT
footprint CAP-1206 (1206 (3216M) Capacitor)
pins: 1, 2

## 1206B222K500CT
designator C?  Capacitance: 2.2nF  (hidden comment: *)
Capacitor, Ceramic (MLCC), 2.2nF, ±10%, 50V, X7R, ±10%, SMD 1206; Manufacturer: Walsin Tech Corp; Manufacturer Part Number: 1206B222K500CT
footprint CAP-1206 (1206 (3216M) Capacitor)
pins: 1, 2

## 1206B222K500NT
designator C?  Capacitance: 2.2nF  (hidden comment: *)
Capacitor, Ceramic (MLCC), 2.2nF, ±10%, 50V, X7R, ±10%, SMD 1206; Manufacturer: FH(Guangdong Fenghua Advanced Tech); Manufacturer Part Number: 1206B222K500NT
footprint CAP-1206 (1206 (3216M) Capacitor)
pins: 1, 2

## 1206B222K501CT
designator C?  Capacitance: 2.2nF  (hidden comment: *)
Capacitor, Ceramic (MLCC), 2.2nF, ±10%, 500V, X7R, ±10%, SMD 1206; Manufacturer: Walsin Tech Corp; Manufacturer Part Number: 1206B222K501CT
footprint CAP-1206 (1206 (3216M) Capacitor)
pins: 1, 2

## 1206B222K501NT
designator C?  Capacitance: 2.2nF  (hidden comment: *)
Capacitor, Ceramic (MLCC), 2.2nF, ±10%, 500V, ±10%, SMD 1206; Manufacturer: FH (Guangdong Fenghua Advanced Tech); Manufacturer Part Number: 1206B222K501NT
footprint CAP-1206 (1206 (3216M) Capacitor)
pins: 1, 2

## 1206B222K631CT
designator C?  Capacitance: 2.2nF  (hidden comment: *)
Capacitor, Ceramic (MLCC), 2.2nF, ±10%, 630V, X7R, ±10%, SMD 1206; Manufacturer: Walsin Tech Corp; Manufacturer Part Number: 1206B222K631CT
footprint CAP-1206 (1206 (3216M) Capacitor)
pins: 1, 2

## 1206B223K101CT
designator C?  Capacitance: 22nF  (hidden comment: *)
Capacitor, Ceramic (MLCC), 22nF, ±10%, 100V, X7R, ±10%, SMD 1206; Manufacturer: Walsin Tech Corp; Manufacturer Part Number: 1206B223K101CT
footprint CAP-1206 (1206 (3216M) Capacitor)
pins: 1, 2

## 1206B223K101NT
designator C?  Capacitance: 22nF  (hidden comment: *)
Capacitor, Ceramic (MLCC), 22nF, ±10%, 100V, X7R, ±10%, SMD 1206; Manufacturer: FH(Guangdong Fenghua Advanced Tech); Manufacturer Part Number: 1206B223K101NT
footprint CAP-1206 (1206 (3216M) Capacitor)
pins: 1, 2

## 1206B223K251CT
designator C?  Capacitance: 22nF  (hidden comment: *)
Capacitor, Ceramic (MLCC), 22nF, ±10%, 250V, X7R, ±10%, SMD 1206; Manufacturer: Walsin Tech Corp; Manufacturer Part Number: 1206B223K251CT
footprint CAP-1206 (1206 (3216M) Capacitor)
pins: 1, 2

## 1206B223K500CT
designator C?  Capacitance: 22nF  (hidden comment: *)
Capacitor, Ceramic (MLCC), 22nF, ±10%, 50V, X7R, ±10%, SMD 1206; Manufacturer: Walsin Tech Corp; Manufacturer Part Number: 1206B223K500CT
footprint CAP-1206 (1206 (3216M) Capacitor)
pins: 1, 2

## 1206B223K500NT
designator C?  Capacitance: 22nF  (hidden comment: *)
Capacitor, Ceramic (MLCC), 22nF, ±10%, 50V, X7R, ±10%, SMD 1206; Manufacturer: FH(Guangdong Fenghua Advanced Tech); Manufacturer Part Number: 1206B223K500NT
footprint CAP-1206 (1206 (3216M) Capacitor)
pins: 1, 2

## 1206B223K501CT
designator C?  Capacitance: 22nF  (hidden comment: *)
Capacitor, Ceramic (MLCC), 22nF, ±10%, 500V, X7R, ±10%, SMD 1206; Manufacturer: Walsin Tech Corp; Manufacturer Part Number: 1206B223K501CT
footprint CAP-1206 (1206 (3216M) Capacitor)
pins: 1, 2

## 1206B223K631CT
designator C?  Capacitance: 22nF  (hidden comment: *)
Capacitor, Ceramic (MLCC), 22nF, ±10%, 630V, X7R, ±10%, SMD 1206; Manufacturer: Walsin Tech Corp; Manufacturer Part Number: 1206B223K631CT
footprint CAP-1206 (1206 (3216M) Capacitor)
pins: 1, 2

## 1206B223K631NT
designator C?  Capacitance: 22nF  (hidden comment: *)
Capacitor, Ceramic (MLCC), 22nF, ±10%, 630V, X7R, ±10%, SMD 1206; Manufacturer: FH(Guangdong Fenghua Advanced Tech); Manufacturer Part Number: 1206B223K631NT
footprint CAP-1206 (1206 (3216M) Capacitor)
pins: 1, 2

## 1206B224K101CT
designator C?  Capacitance: 220nF  (hidden comment: *)
Capacitor, Ceramic (MLCC), 220nF, ±10%, 100V, X7R, ±10%, SMD 1206; Manufacturer: Walsin Tech Corp; Manufacturer Part Number: 1206B224K101CT
footprint CAP-1206 (1206 (3216M) Capacitor)
pins: 1, 2

## 1206B224K101NT
designator C?  Capacitance: 220nF  (hidden comment: *)
Capacitor, Ceramic (MLCC), 220nF, ±10%, 100V, ±10%, SMD 1206; Manufacturer: FH(Guangdong Fenghua Advanced Tech); Manufacturer Part Number: 1206B224K101NT
footprint CAP-1206 (1206 (3216M) Capacitor)
pins: 1, 2

## 1206B224K251NT
designator C?  Capacitance: 220nF  (hidden comment: *)
Capacitor, Ceramic (MLCC), 220nF, ±10%, 250V, ±10%, SMD 1206; Manufacturer: FH(Guangdong Fenghua Advanced Tech); Manufacturer Part Number: 1206B224K251NT
footprint CAP-1206 (1206 (3216M) Capacitor)
pins: 1, 2

## 1206B224K500CT
designator C?  Capacitance: 220nF  (hidden comment: *)
Capacitor, Ceramic (MLCC), 220nF, ±10%, 50V, X7R, ±10%, SMD 1206; Manufacturer: Walsin Tech Corp; Manufacturer Part Number: 1206B224K500CT
footprint CAP-1206 (1206 (3216M) Capacitor)
pins: 1, 2

## 1206B225K160CT
designator C?  Capacitance: 2.2uF  (hidden comment: *)
Capacitor, Ceramic (MLCC), 2.2uF, ±10%, 16V, X7R, ±10%, SMD 1206; Manufacturer: Walsin Tech Corp; Manufacturer Part Number: 1206B225K160CT
footprint CAP-1206 (1206 (3216M) Capacitor)
pins: 1, 2

## 1206B225K160NT
designator C?  Capacitance: 2.2uF  (hidden comment: *)
Capacitor, Ceramic (MLCC), 2.2uF, ±10%, 16V, X5R, ±10%, SMD 1206; Manufacturer: FH(Guangdong Fenghua Advanced Tech); Manufacturer Part Number: 1206B225K160NT
footprint CAP-1206 (1206 (3216M) Capacitor)
pins: 1, 2

## 1206B225K250CT
designator C?  Capacitance: 2.2uF  (hidden comment: *)
Capacitor, Ceramic (MLCC), 2.2uF, ±10%, 25V, X7R, ±10%, SMD 1206; Manufacturer: Walsin Tech Corp; Manufacturer Part Number: 1206B225K250CT
footprint CAP-1206 (1206 (3216M) Capacitor)
pins: 1, 2

## 1206B225K250NT
designator C?  Capacitance: 2.2uF  (hidden comment: *)
Capacitor, Ceramic (MLCC), 2.2uF, ±10%, 25V, X7R, ±10%, SMD 1206; Manufacturer: FH(Guangdong Fenghua Advanced Tech); Manufacturer Part Number: 1206B225K250NT
footprint CAP-1206 (1206 (3216M) Capacitor)
pins: 1, 2

## 1206B225K500CT
designator C?  Capacitance: 2.2uF  (hidden comment: *)
Capacitor, Ceramic (MLCC), 2.2uF, ±10%, 50V, X7R, ±10%, SMD 1206; Manufacturer: Walsin Tech Corp; Manufacturer Part Number: 1206B225K500CT
footprint CAP-1206 (1206 (3216M) Capacitor)
pins: 1, 2

## 1206B225K500NT
designator C?  Capacitance: 2.2uF  (hidden comment: *)
Capacitor, Ceramic (MLCC), 2.2uF, ±10%, 50V, X7R, ±10%, SMD 1206; Manufacturer: FH(Guangdong Fenghua Advanced Tech); Manufacturer Part Number: 1206B225K500NT
footprint CAP-1206 (1206 (3216M) Capacitor)
pins: 1, 2

## 1206B225K500NT_C410824
designator C?  Capacitance: 2.2uF  (hidden comment: *)
Capacitor, Ceramic (MLCC), 2.2uF, ±10%, 50V, X7R, ±10%, SMD 1206; Manufacturer: FH(Guangdong Fenghua Advanced Tech); Manufacturer Part Number: 1206B225K500NT
footprint CAP-1206 (1206 (3216M) Capacitor)
pins: 1, 2

## 1206B226K100NT
designator C?  Capacitance: 22uF  (hidden comment: *)
Capacitor, Ceramic (MLCC), 22uF, ±10%, 10V, X7R, ±10%, SMD 1206; Manufacturer: FH(Guangdong Fenghua Advanced Tech); Manufacturer Part Number: 1206B226K100NT
footprint CAP-1206 (1206 (3216M) Capacitor)
pins: 1, 2

## 1206B272K500NT
designator C?  Capacitance: 2.7nF  (hidden comment: *)
Capacitor, Ceramic (MLCC), 2.7nF, ±10%, 50V, X7R, ±10%, SMD 1206; Manufacturer: FH(Guangdong Fenghua Advanced Tech); Manufacturer Part Number: 1206B272K500NT
footprint CAP-1206 (1206 (3216M) Capacitor)
pins: 1, 2

## 1206B273K500CT
designator C?  Capacitance: 27nF  (hidden comment: *)
Capacitor, Ceramic (MLCC), 27nF, ±10%, 50V, X7R, ±10%, SMD 1206; Manufacturer: Walsin Tech Corp; Manufacturer Part Number: 1206B273K500CT
footprint CAP-1206 (1206 (3216M) Capacitor)
pins: 1, 2

## 1206B301K500NT
designator C?  Capacitance: 300pF  (hidden comment: *)
Capacitor, Ceramic (MLCC), 300pF, ±10%, 50V, X7R, ±10%, SMD 1206; Manufacturer: FH(Guangdong Fenghua Advanced Tech); Manufacturer Part Number: 1206B301K500NT
footprint CAP-1206 (1206 (3216M) Capacitor)
pins: 1, 2

## 1206B331K101CT
designator C?  Capacitance: 330pF  (hidden comment: *)
Capacitor, Ceramic (MLCC), 330pF, ±10%, 100V, X7R, ±10%, SMD 1206; Manufacturer: Walsin Tech Corp; Manufacturer Part Number: 1206B331K101CT
footprint CAP-1206 (1206 (3216M) Capacitor)
pins: 1, 2

## 1206B331K102CT
designator C?  Capacitance: 330pF  (hidden comment: *)
Capacitor, Ceramic (MLCC), 330pF, ±10%, 1kV, X7R, ±10%, SMD 1206; Manufacturer: Walsin Tech Corp; Manufacturer Part Number: 1206B331K102CT
footprint CAP-1206 (1206 (3216M) Capacitor)
pins: 1, 2

## 1206B331K102NT
designator C?  Capacitance: 330pF  (hidden comment: *)
Capacitor, Ceramic (MLCC), 330pF, ±10%, 1kV, X7R, ±10%, SMD 1206; Manufacturer: FH(Guangdong Fenghua Advanced Tech); Manufacturer Part Number: 1206B331K102NT
footprint CAP-1206 (1206 (3216M) Capacitor)
pins: 1, 2

## 1206B331K201CT
designator C?  Capacitance: 330pF  (hidden comment: *)
Capacitor, Ceramic (MLCC), 330pF, ±10%, 200V, X7R, ±10%, SMD 1206; Manufacturer: Walsin Tech Corp; Manufacturer Part Number: 1206B331K201CT
footprint CAP-1206 (1206 (3216M) Capacitor)
pins: 1, 2

## 1206B331K201NT
designator C?  Capacitance: 330pF  (hidden comment: *)
Capacitor, Ceramic (MLCC), 330pF, ±10%, 200V, ±10%, SMD 1206; Manufacturer: FH(Guangdong Fenghua Advanced Tech); Manufacturer Part Number: 1206B331K201NT
footprint CAP-1206 (1206 (3216M) Capacitor)
pins: 1, 2

## 1206B331K500CT
designator C?  Capacitance: 330pF  (hidden comment: *)
Capacitor, Ceramic (MLCC), 330pF, ±10%, 50V, X7R, ±10%, SMD 1206; Manufacturer: Walsin Tech Corp; Manufacturer Part Number: 1206B331K500CT
footprint CAP-1206 (1206 (3216M) Capacitor)
pins: 1, 2

## 1206B331K500NT
designator C?  Capacitance: 330pF  (hidden comment: *)
Capacitor, Ceramic (MLCC), 330pF, ±10%, 50V, X7R, ±10%, SMD 1206; Manufacturer: FH(Guangdong Fenghua Advanced Tech); Manufacturer Part Number: 1206B331K500NT
footprint CAP-1206 (1206 (3216M) Capacitor)
pins: 1, 2

## 1206B331K501NT
designator C?  Capacitance: 330pF  (hidden comment: *)
Capacitor, Ceramic (MLCC), 330pF, ±10%, 500V, X7R, ±10%, SMD 1206; Manufacturer: FH(Guangdong Fenghua Advanced Tech); Manufacturer Part Number: 1206B331K501NT
footprint CAP-1206 (1206 (3216M) Capacitor)
pins: 1, 2

## 1206B332J501CT
designator C?  Capacitance: 3.3nF  (hidden comment: *)
Capacitor, Ceramic (MLCC), 3.3nF, ±5%, 500V, X7R, ±5%, SMD 1206; Manufacturer: Walsin Tech Corp; Manufacturer Part Number: 1206B332J501CT
footprint CAP-1206 (1206 (3216M) Capacitor)
pins: 1, 2

## 1206B332K102CT
designator C?  Capacitance: 3.3nF  (hidden comment: *)
Capacitor, Ceramic (MLCC), 3.3nF, ±10%, 1kV, X7R, ±10%, SMD 1206; Manufacturer: Walsin Tech Corp; Manufacturer Part Number: 1206B332K102CT
footprint CAP-1206 (1206 (3216M) Capacitor)
pins: 1, 2

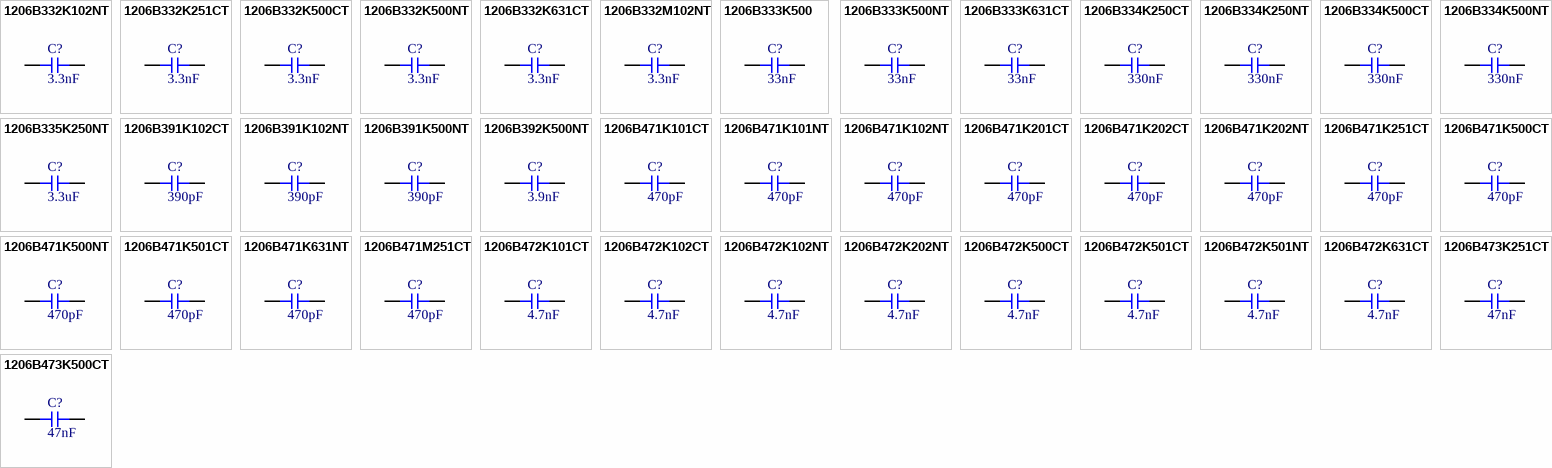
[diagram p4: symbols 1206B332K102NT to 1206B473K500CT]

## 1206B332K102NT
designator C?  Capacitance: 3.3nF  (hidden comment: *)
Capacitor, Ceramic (MLCC), 3.3nF, ±10%, 1kV, X7R, ±10%, SMD 1206; Manufacturer: FH(Guangdong Fenghua Advanced Tech); Manufacturer Part Number: 1206B332K102NT
footprint CAP-1206 (1206 (3216M) Capacitor)
pins: 1, 2

## 1206B332K251CT
designator C?  Capacitance: 3.3nF  (hidden comment: *)
Capacitor, Ceramic (MLCC), 3.3nF, ±10%, 250V, X7R, ±10%, SMD 1206; Manufacturer: Walsin Tech Corp; Manufacturer Part Number: 1206B332K251CT
footprint CAP-1206 (1206 (3216M) Capacitor)
pins: 1, 2

## 1206B332K500CT
designator C?  Capacitance: 3.3nF  (hidden comment: *)
Capacitor, Ceramic (MLCC), 3.3nF, ±10%, 50V, X7R, ±10%, SMD 1206; Manufacturer: Walsin Tech Corp; Manufacturer Part Number: 1206B332K500CT
footprint CAP-1206 (1206 (3216M) Capacitor)
pins: 1, 2

## 1206B332K500NT
designator C?  Capacitance: 3.3nF  (hidden comment: *)
Capacitor, Ceramic (MLCC), 3.3nF, ±10%, 50V, X7R, ±10%, SMD 1206; Manufacturer: FH(Guangdong Fenghua Advanced Tech); Manufacturer Part Number: 1206B332K500NT
footprint CAP-1206 (1206 (3216M) Capacitor)
pins: 1, 2

## 1206B332K631CT
designator C?  Capacitance: 3.3nF  (hidden comment: *)
Capacitor, Ceramic (MLCC), 3.3nF, ±10%, 630V, X7R, ±10%, SMD 1206; Manufacturer: Walsin Tech Corp; Manufacturer Part Number: 1206B332K631CT
footprint CAP-1206 (1206 (3216M) Capacitor)
pins: 1, 2

## 1206B332M102NT
designator C?  Capacitance: 3.3nF  (hidden comment: *)
Capacitor, Ceramic (MLCC), 3.3nF, ±20%, 1kV, ±20%, SMD 1206; Manufacturer: FH-BK(Guangdong Fenghua Bangke Elec); Manufacturer Part Number: 1206B332M102NT
footprint CAP-1206 (1206 (3216M) Capacitor)
pins: 1, 2

## 1206B333K500
designator C?  Capacitance: 33nF  (hidden comment: *)
Capacitor, Ceramic (MLCC), 33nF, ±10%, 50V, X7R, ±10%, SMD 1206; Manufacturer: Walsin Tech Corp; Manufacturer Part Number: 1206B333K500
footprint CAP-1206 (1206 (3216M) Capacitor)
pins: 1, 2

## 1206B333K500NT
designator C?  Capacitance: 33nF  (hidden comment: *)
Capacitor, Ceramic (MLCC), 33nF, ±10%, 50V, X7R, ±10%, SMD 1206; Manufacturer: FH(Guangdong Fenghua Advanced Tech); Manufacturer Part Number: 1206B333K500NT
footprint CAP-1206 (1206 (3216M) Capacitor)
pins: 1, 2

## 1206B333K631CT
designator C?  Capacitance: 33nF  (hidden comment: *)
Capacitor, Ceramic (MLCC), 33nF, ±10%, 630V, X7R, ±10%, SMD 1206; Manufacturer: Walsin Tech Corp; Manufacturer Part Number: 1206B333K631CT
footprint CAP-1206 (1206 (3216M) Capacitor)
pins: 1, 2

## 1206B334K250CT
designator C?  Capacitance: 330nF  (hidden comment: *)
Capacitor, Ceramic (MLCC), 330nF, ±10%, 25V, X7R, ±10%, SMD 1206; Manufacturer: Walsin Tech Corp; Manufacturer Part Number: 1206B334K250CT
footprint CAP-1206 (1206 (3216M) Capacitor)
pins: 1, 2

## 1206B334K250NT
designator C?  Capacitance: 330nF  (hidden comment: *)
Capacitor, Ceramic (MLCC), 330nF, ±10%, 25V, ±10%, SMD 1206; Manufacturer: FH(Guangdong Fenghua Advanced Tech); Manufacturer Part Number: 1206B334K250NT
footprint CAP-1206 (1206 (3216M) Capacitor)
pins: 1, 2

## 1206B334K500CT
designator C?  Capacitance: 330nF  (hidden comment: *)
Capacitor, Ceramic (MLCC), 330nF, ±10%, 50V, X7R, ±10%, SMD 1206; Manufacturer: Walsin Tech Corp; Manufacturer Part Number: 1206B334K500CT
footprint CAP-1206 (1206 (3216M) Capacitor)
pins: 1, 2

## 1206B334K500NT
designator C?  Capacitance: 330nF  (hidden comment: *)
Capacitor, Ceramic (MLCC), 330nF, ±10%, 50V, X7R, ±10%, SMD 1206; Manufacturer: FH(Guangdong Fenghua Advanced Tech); Manufacturer Part Number: 1206B334K500NT
footprint CAP-1206 (1206 (3216M) Capacitor)
pins: 1, 2

## 1206B335K250NT
designator C?  Capacitance: 3.3uF  (hidden comment: *)
Capacitor, Ceramic (MLCC), 3.3uF, ±10%, 25V, ±10%, SMD 1206; Manufacturer: FH(Guangdong Fenghua Advanced Tech); Manufacturer Part Number: 1206B335K250NT
footprint CAP-1206 (1206 (3216M) Capacitor)
pins: 1, 2

## 1206B391K102CT
designator C?  Capacitance: 390pF  (hidden comment: *)
Capacitor, Ceramic (MLCC), 390pF, ±10%, 1kV, X7R, ±10%, SMD 1206; Manufacturer: Walsin Tech Corp; Manufacturer Part Number: 1206B391K102CT
footprint CAP-1206 (1206 (3216M) Capacitor)
pins: 1, 2

## 1206B391K102NT
designator C?  Capacitance: 390pF  (hidden comment: *)
Capacitor, Ceramic (MLCC), 390pF, ±10%, 1kV, X7R, ±10%, SMD 1206; Manufacturer: FH(Guangdong Fenghua Advanced Tech); Manufacturer Part Number: 1206B391K102NT
footprint CAP-1206 (1206 (3216M) Capacitor)
pins: 1, 2

## 1206B391K500NT
designator C?  Capacitance: 390pF  (hidden comment: *)
Capacitor, Ceramic (MLCC), 390pF, ±10%, 50V, X7R, ±10%, SMD 1206; Manufacturer: FH(Guangdong Fenghua Advanced Tech); Manufacturer Part Number: 1206B391K500NT
footprint CAP-1206 (1206 (3216M) Capacitor)
pins: 1, 2

## 1206B392K500NT
designator C?  Capacitance: 3.9nF  (hidden comment: *)
Capacitor, Ceramic (MLCC), 3.9nF, ±10%, 50V, X7R, ±10%, SMD 1206; Manufacturer: FH(Guangdong Fenghua Advanced Tech); Manufacturer Part Number: 1206B392K500NT
footprint CAP-1206 (1206 (3216M) Capacitor)
pins: 1, 2

## 1206B471K101CT
designator C?  Capacitance: 470pF  (hidden comment: *)
Capacitor, Ceramic (MLCC), 470pF, ±10%, 100V, X7R, ±10%, SMD 1206; Manufacturer: Walsin Tech Corp; Manufacturer Part Number: 1206B471K101CT
footprint CAP-1206 (1206 (3216M) Capacitor)
pins: 1, 2

## 1206B471K101NT
designator C?  Capacitance: 470pF  (hidden comment: *)
Capacitor, Ceramic (MLCC), 470pF, ±10%, 100V, X7R, ±10%, SMD 1206; Manufacturer: FH(Guangdong Fenghua Advanced Tech); Manufacturer Part Number: 1206B471K101NT
footprint CAP-1206 (1206 (3216M) Capacitor)
pins: 1, 2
